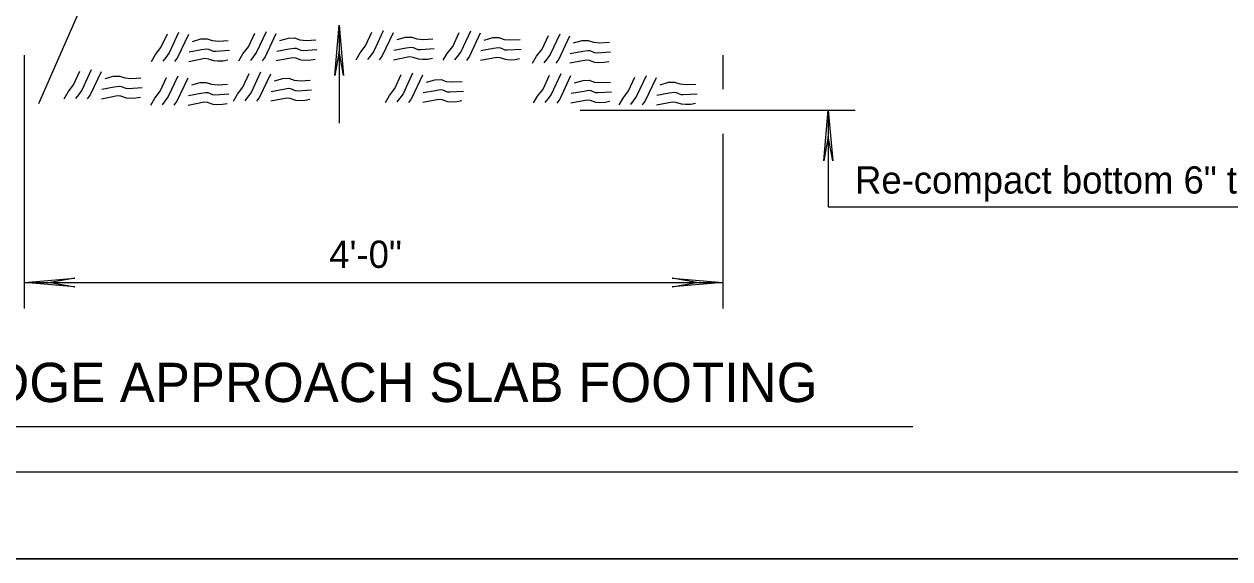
# Model space of a CAD drawing. Extents: x 1000 to 1036, y 1000 to 1022.7.
# Drawn here: x 1012.07 to 1018.98, y 1000 to 1003.06 of the extents above; entities that cross this region are included whole.
import ezdxf

# ---------------------------------------------------------------- set-up
doc = ezdxf.new("R2010")
doc.units = 0
for name, color, linetype in [('KS_Borders_Z_N', 7, 'Continuous'), ('KS_PlotShape_z_e', 7, 'Continuous'), ('rd_Area Patterns Normal_z_n', 7, 'Continuous'), ('rd_Detail Annotation_z_n', 7, 'Continuous'), ('rd_Dimensions_z_n', 7, 'Continuous'), ('rd_Misc Label_z_n', 7, 'Continuous')]:
    doc.layers.add(name, color=color, linetype=linetype)

msp = doc.modelspace()

# ---------------------------------------------------------------- linework, layer by layer
at = {"layer": 'KS_Borders_Z_N'}
for points in [[(999.998, 1021.998), (1035.9979, 1021.998), (1035.9979, 999.998), (999.998, 999.998)], [(1001.998, 1000.498), (1035.4979, 1000.498), (1035.4979, 1021.498), (1001.998, 1021.498)]]:
    msp.add_lwpolyline(points, close=True, dxfattribs=at)
at = {"layer": 'KS_PlotShape_z_e'}
msp.add_lwpolyline([(999.998, 999.998), (1035.9979, 999.998), (1035.9979, 1021.998), (999.998, 1021.998)], close=True, dxfattribs=at)
at = {"layer": 'rd_Area Patterns Normal_z_n'}
for points in [[(1014.1309, 1003.0254), (1014.0761, 1002.9085), (1014.0569, 1002.8823), (1014.0404, 1002.8611)], [(1014.6296, 1003.0229), (1014.5748, 1002.9059), (1014.5556, 1002.8797), (1014.5391, 1002.8585)], [(1012.8032, 1002.8495), (1012.8262, 1002.8889), (1012.8572, 1002.9295), (1012.8939, 1003.0082)], [(1012.9587, 1003.0158), (1012.9039, 1002.8989), (1012.8848, 1002.8727), (1012.8682, 1002.8515)], [(1013.0148, 1003.0047), (1012.9528, 1002.8724), (1012.9358, 1002.8491)], [(1013.0381, 1002.9652), (1013.0864, 1002.9792), (1013.1214, 1002.9801), (1013.1511, 1002.9696), (1013.189, 1002.9661), (1013.2429, 1002.9691)], [(1013.3042, 1002.8538), (1013.3272, 1002.8932), (1013.3582, 1002.9338), (1013.3949, 1003.0125)], [(1013.4598, 1003.0201), (1013.405, 1002.9032), (1013.3858, 1002.877), (1013.3693, 1002.8558)], [(1013.5159, 1003.009), (1013.4538, 1002.8767), (1013.4369, 1002.8534)], [(1013.5391, 1002.9695), (1013.5874, 1002.9835), (1013.6225, 1002.9844), (1013.6522, 1002.9739), (1013.6901, 1002.9704), (1013.7439, 1002.9734)], [(1013.9753, 1002.8591), (1013.9983, 1002.8985), (1014.0294, 1002.939), (1014.066, 1003.0178)], [(1014.187, 1003.0143), (1014.125, 1002.882), (1014.108, 1002.8586)], [(1014.2102, 1002.9748), (1014.2585, 1002.9888), (1014.2936, 1002.9897), (1014.3233, 1002.9791), (1014.3612, 1002.9757), (1014.4151, 1002.9786)], [(1014.474, 1002.8566), (1014.497, 1002.8959), (1014.5281, 1002.9365), (1014.5647, 1003.0152)], [(1014.6857, 1003.0117), (1014.6236, 1002.8795), (1014.6067, 1002.8561)], [(1014.7089, 1002.9722), (1014.7572, 1002.9863), (1014.7923, 1002.9872), (1014.822, 1002.9766), (1014.8599, 1002.9732), (1014.9137, 1002.9761)], [(1014.9857, 1002.8402), (1015.0087, 1002.8796), (1015.0397, 1002.9202), (1015.0764, 1002.9989)], [(1015.1413, 1003.0066), (1015.0865, 1002.8896), (1015.0673, 1002.8634), (1015.0508, 1002.8422)], [(1015.1974, 1002.9954), (1015.1353, 1002.8632), (1015.1184, 1002.8398)], [(1015.2206, 1002.9559), (1015.2689, 1002.97), (1015.304, 1002.9708), (1015.3337, 1002.9603), (1015.3716, 1002.9569), (1015.4254, 1002.9598)], [(1013.0191, 1002.9051), (1013.0901, 1002.9182), (1013.1187, 1002.9225), (1013.1302, 1002.9211), (1013.1566, 1002.9096), (1013.1709, 1002.9089), (1013.2497, 1002.9139)], [(1013.5201, 1002.9095), (1013.5911, 1002.9225), (1013.6198, 1002.9268), (1013.6312, 1002.9254), (1013.6577, 1002.9139), (1013.672, 1002.9132), (1013.7507, 1002.9182)], [(1014.1913, 1002.9147), (1014.2623, 1002.9278), (1014.2909, 1002.9321), (1014.3023, 1002.9307), (1014.3288, 1002.9192), (1014.3431, 1002.9185), (1014.4218, 1002.9234)], [(1014.6899, 1002.9122), (1014.761, 1002.9252), (1014.7896, 1002.9296), (1014.801, 1002.9281), (1014.8275, 1002.9167), (1014.8418, 1002.916), (1014.9205, 1002.9209)], [(1015.2016, 1002.8959), (1015.2726, 1002.9089), (1015.3013, 1002.9133), (1015.3127, 1002.9118), (1015.3392, 1002.9004), (1015.3535, 1002.8997), (1015.4322, 1002.9046)], [(1013.2403, 1002.8575), (1013.2138, 1002.8524), (1013.1831, 1002.8509), (1013.1602, 1002.8531), (1013.1288, 1002.8638), (1013.1095, 1002.866), (1013.0168, 1002.8483)], [(1013.7413, 1002.8618), (1013.7149, 1002.8567), (1013.6841, 1002.8552), (1013.6613, 1002.8574), (1013.6298, 1002.8681), (1013.6105, 1002.8703), (1013.5179, 1002.8526)], [(1014.4125, 1002.8671), (1014.386, 1002.862), (1014.3553, 1002.8605), (1014.3324, 1002.8627), (1014.3009, 1002.8734), (1014.2816, 1002.8756), (1014.189, 1002.8579)], [(1014.9111, 1002.8646), (1014.8847, 1002.8594), (1014.8539, 1002.858), (1014.8311, 1002.8602), (1014.7996, 1002.8709), (1014.7803, 1002.873), (1014.6877, 1002.8554)], [(1015.4228, 1002.8483), (1015.3964, 1002.8431), (1015.3656, 1002.8417), (1015.3428, 1002.8438), (1015.3113, 1002.8546), (1015.292, 1002.8567), (1015.1994, 1002.8391)], [(1012.3026, 1002.6357), (1012.3257, 1002.6751), (1012.3567, 1002.7156), (1012.3934, 1002.7943)], [(1012.4582, 1002.802), (1012.4034, 1002.685), (1012.3843, 1002.6589), (1012.3677, 1002.6377)], [(1012.5143, 1002.7908), (1012.4523, 1002.6586), (1012.4353, 1002.6352)], [(1012.5375, 1002.7513), (1012.5859, 1002.7654), (1012.6209, 1002.7663), (1012.6506, 1002.7557), (1012.6885, 1002.7523), (1012.7424, 1002.7552)], [(1012.7989, 1002.5995), (1012.8219, 1002.6388), (1012.8529, 1002.6794), (1012.8896, 1002.7581)], [(1012.9544, 1002.7658), (1012.8996, 1002.6488), (1012.8805, 1002.6226), (1012.864, 1002.6015)], [(1013.0105, 1002.7546), (1012.9485, 1002.6224), (1012.9315, 1002.599)], [(1013.2723, 1002.6228), (1013.2953, 1002.6621), (1013.3263, 1002.7027), (1013.363, 1002.7814)], [(1013.4279, 1002.7891), (1013.3731, 1002.6721), (1013.3539, 1002.6459), (1013.3374, 1002.6248)], [(1013.484, 1002.7779), (1013.4219, 1002.6457), (1013.405, 1002.6223)], [(1013.5072, 1002.7384), (1013.5555, 1002.7525), (1013.5906, 1002.7534), (1013.6203, 1002.7428), (1013.6582, 1002.7394), (1013.712, 1002.7423)], [(1014.1431, 1002.6155), (1014.1661, 1002.6549), (1014.1971, 1002.6954), (1014.2338, 1002.7742)], [(1014.2986, 1002.7818), (1014.2438, 1002.6649), (1014.2247, 1002.6387), (1014.2082, 1002.6175)], [(1014.3547, 1002.7707), (1014.2927, 1002.6384), (1014.2757, 1002.615)], [(1014.378, 1002.7312), (1014.4263, 1002.7452), (1014.4614, 1002.7461), (1014.491, 1002.7356), (1014.5289, 1002.7321), (1014.5828, 1002.7351)], [(1014.9914, 1002.6117), (1015.0144, 1002.6511), (1015.0454, 1002.6916), (1015.0821, 1002.7703)], [(1015.147, 1002.778), (1015.0922, 1002.661), (1015.073, 1002.6349), (1015.0565, 1002.6137)], [(1015.2031, 1002.7668), (1015.141, 1002.6346), (1015.1241, 1002.6112)], [(1015.4808, 1002.6007), (1015.5039, 1002.6401), (1015.5349, 1002.6807), (1015.5716, 1002.7594)], [(1015.6364, 1002.7671), (1015.5816, 1002.6501), (1015.5625, 1002.6239), (1015.5459, 1002.6027)], [(1015.6925, 1002.7559), (1015.6305, 1002.6236), (1015.6135, 1002.6003)], [(1012.5186, 1002.6913), (1012.5896, 1002.7043), (1012.6182, 1002.7087), (1012.6296, 1002.7072), (1012.6561, 1002.6958), (1012.6704, 1002.6951), (1012.7491, 1002.7)], [(1013.0338, 1002.7151), (1013.0821, 1002.7292), (1013.1172, 1002.7301), (1013.1469, 1002.7195), (1013.1847, 1002.7161), (1013.2386, 1002.719)], [(1013.4882, 1002.6784), (1013.5593, 1002.6914), (1013.5879, 1002.6958), (1013.5993, 1002.6943), (1013.6258, 1002.6829), (1013.6401, 1002.6822), (1013.7188, 1002.6871)], [(1014.359, 1002.6711), (1014.43, 1002.6842), (1014.4586, 1002.6885), (1014.4701, 1002.6871), (1014.4965, 1002.6756), (1014.5109, 1002.6749), (1014.5896, 1002.6799)], [(1015.2073, 1002.6673), (1015.2783, 1002.6803), (1015.307, 1002.6847), (1015.3184, 1002.6832), (1015.3449, 1002.6718), (1015.3592, 1002.6711), (1015.4379, 1002.676)], [(1015.2263, 1002.7273), (1015.2746, 1002.7414), (1015.3097, 1002.7423), (1015.3394, 1002.7317), (1015.3773, 1002.7283), (1015.4311, 1002.7312)], [(1015.7157, 1002.7164), (1015.7641, 1002.7304), (1015.7991, 1002.7313), (1015.8288, 1002.7208), (1015.8667, 1002.7173), (1015.9206, 1002.7203)], [(1012.7398, 1002.6437), (1012.7133, 1002.6386), (1012.6826, 1002.6371), (1012.6597, 1002.6393), (1012.6283, 1002.65), (1012.6089, 1002.6521), (1012.5163, 1002.6345)], [(1013.236, 1002.6075), (1013.2095, 1002.6023), (1013.1788, 1002.6009), (1013.1559, 1002.6031), (1013.1245, 1002.6138), (1013.1052, 1002.6159), (1013.0125, 1002.5983)], [(1013.0148, 1002.6551), (1013.0858, 1002.6681), (1013.1144, 1002.6725), (1013.1259, 1002.671), (1013.1523, 1002.6596), (1013.1667, 1002.6589), (1013.2454, 1002.6638)], [(1013.7094, 1002.6308), (1013.683, 1002.6256), (1013.6522, 1002.6242), (1013.6294, 1002.6264), (1013.5979, 1002.6371), (1013.5786, 1002.6392), (1013.486, 1002.6216)], [(1014.5802, 1002.6235), (1014.5537, 1002.6184), (1014.523, 1002.6169), (1014.5001, 1002.6191), (1014.4687, 1002.6298), (1014.4494, 1002.632), (1014.3567, 1002.6143)], [(1015.4285, 1002.6197), (1015.4021, 1002.6145), (1015.3713, 1002.6131), (1015.3485, 1002.6153), (1015.317, 1002.626), (1015.2977, 1002.6281), (1015.2051, 1002.6105)], [(1015.918, 1002.6088), (1015.8915, 1002.6036), (1015.8608, 1002.6022), (1015.8379, 1002.6043), (1015.8065, 1002.615), (1015.7872, 1002.6172), (1015.6945, 1002.5996)], [(1015.6968, 1002.6564), (1015.7678, 1002.6694), (1015.7964, 1002.6737), (1015.8078, 1002.6723), (1015.8343, 1002.6609), (1015.8486, 1002.6601), (1015.9274, 1002.6651)]]:
    msp.add_lwpolyline(points, dxfattribs=at)
at = {"layer": 'rd_Detail Annotation_z_n'}
for p, q in [((1013.0876, 1004.7365), (1012.1563, 1002.6063)), ((1011.2298, 1000.7578), (1017.1638, 1000.7578))]:
    msp.add_line(p, q, dxfattribs=at)
at = {"layer": 'rd_Dimensions_z_n'}
for p, q in [((1013.8776, 1003.0582), (1013.8776, 1002.497)), ((1012.0749, 1002.8854), (1012.0749, 1001.4333)), ((1016.0746, 1002.8854), (1016.0746, 1002.6913)), ((1015.2583, 1002.57), (1016.8338, 1002.57)), ((1016.6793, 1002.57), (1016.6793, 1002.0157)), ((1016.0746, 1002.4351), (1016.0746, 1001.4333)), ((1016.6793, 1002.0157), (1021.2965, 1002.0157)), ((1012.0749, 1001.5831), (1016.0746, 1001.5831))]:
    msp.add_line(p, q, dxfattribs=at)
at = {"layer": 'rd_Misc Label_z_n'}
for points in [[(1013.8523, 1002.769), (1013.8776, 1003.0582), (1013.9029, 1002.769), (1013.8776, 1002.9082), (1013.8523, 1002.769)], [(1016.654, 1002.2808), (1016.6793, 1002.57), (1016.7046, 1002.2808), (1016.6793, 1002.42), (1016.654, 1002.2808)], [(1012.3641, 1001.5578), (1012.075, 1001.5831), (1012.3641, 1001.6084), (1012.225, 1001.5831), (1012.3641, 1001.5578)], [(1015.7854, 1001.6084), (1016.0746, 1001.5831), (1015.7854, 1001.5578), (1015.9246, 1001.5831), (1015.7854, 1001.6084)]]:
    msp.add_lwpolyline(points, dxfattribs=at)

# ---------------------------------------------------------------- texts
at = {"layer": 'rd_Detail Annotation_z_n'}
msp.add_text('BRIDGE APPROACH SLAB FOOTING', height=0.225, dxfattribs=at).set_placement((1011.3846, 1000.8972))
at = {"layer": 'rd_Dimensions_z_n'}
for s, p in [('Re-compact bottom 6" to Type "A" Compaction', (1016.8324, 1002.0924)), ('4\'-0"', (1013.8211, 1001.6662))]:
    msp.add_text(s, height=0.15625, dxfattribs=at).set_placement(p)

doc.saveas('drawing.dxf')
